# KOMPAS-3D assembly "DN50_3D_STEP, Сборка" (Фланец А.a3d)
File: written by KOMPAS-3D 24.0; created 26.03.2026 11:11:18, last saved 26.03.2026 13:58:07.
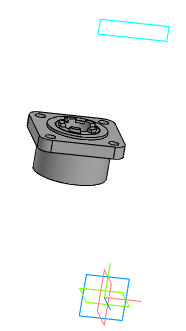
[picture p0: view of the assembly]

Document properties: Автор: R2D2; Полное имя файла: E:\Работа\Зайцев\GVWR2121M-2W-F-ОСТ Задвижка клиновая с видвижным штоком Ду50-300 Ру16\DN50\Исходные материалы\Фланец А.a3d

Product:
- Body: Тело 2  | qty 1
    Масса: 2.709631
- Part/product: DN50_3D_STEP  | designation Сборка
    Масса: 2.725126

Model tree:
1. Перпендикулярная плоскость:2
     Координата Z = -90
2. Операция без истории:2
3. Эскиз:1  (with: Грань.Операция без истории:2, Ребро.Операция без истории:2)
4. Элемент выдавливания:1  (with: Грань.Операция без истории:2)
     Расстояние 2 = 14.5
5. Массив по концентрической сетке:1  (with: Элемент выдавливания:1, Грань.Операция без истории:2)  (4 pattern instances)
     Шаг 2 = 360
6. Скругление:1
     Радиус = 13.5
7. Эскиз:2  (with: Грань.Операция без истории:2, Ребро.Операция без истории:2)
8. Элемент выдавливания:2
     Расстояние 2 = 20
9. Эскиз:3  (with: Грань.Операция без истории:2, Ребро.Операция без истории:2)
10. Элемент выдавливания:3  (with: Грань.Операция без истории:2)
     Расстояние 2 = 3
11. Эскиз:4  (with: Грань.Операция без истории:2, Ребро.Операция без истории:2)
12. Элемент выдавливания:4
     Расстояние 1 = 3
